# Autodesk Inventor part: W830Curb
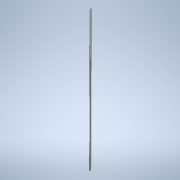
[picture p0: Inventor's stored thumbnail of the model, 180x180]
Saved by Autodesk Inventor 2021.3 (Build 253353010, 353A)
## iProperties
Created: 2021-10
Part Number: W830Curb
Material: Concrete, Cast-in-Place, Gray
Document SubType Name: Modeling
Designer: u1426
Density: 2.40731 g/cm^3
Appearance: Flat - Gray 1
Author: u1426
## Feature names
1. Sweep1
2. Sweep3
## Parameters: d10 = 1016 mm, d43 = 0, d44 = 0, d45 = 0, d59 = 12.7 mm, d63 = 12.7 mm, d126 = 508 mm, d127 = 152.4 mm, d128 = 19.05 mm, d129 = 50.8 mm, d132 = 508 mm, d133 = 508 mm, d138 = 152.4 mm, d139 = 76.2 mm, d140 = 101.6 mm, d145 = 349.25 mm, d146 = 6.35 mm, d147 = 6.35 mm, d148 = 12.7 mm, d149 = 6.35 mm, d150 = 12.7 mm, d151 = 6.35 mm, d152 = 19.05 mm, d153 = 19.05 mm, d154 = 19.05 mm, d155 = 19.05 mm, d158 = 0, d159 = 0, d160 = 64414.4 mm, d161 = 257.6576 mm, d164 = 133.35 mm, d165 = 133.35 mm
